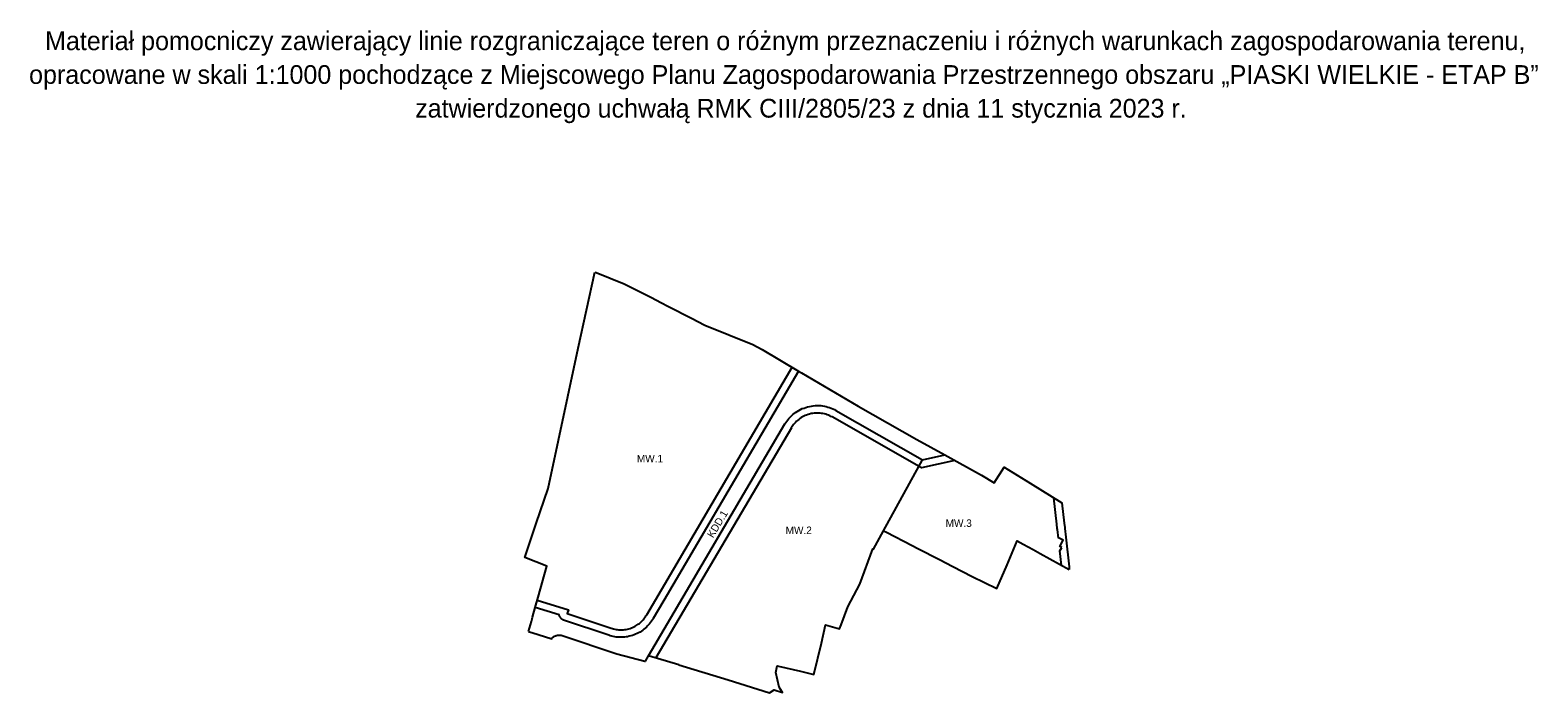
# Model space of a CAD drawing. Extents: x 7427825 to 7429032, y 5541325 to 5541855.
import ezdxf

# ---------------------------------------------------------------- set-up
doc = ezdxf.new("R2010")
doc.units = 0
for name, color, linetype in [('info', 7, 'Continuous'), ('LIN_Linia Zabudowy Nieprzekraczalna', 7, 'Continuous'), ('LIN_linie_rozgraniczajace', 7, 'Continuous'), ('TXT_oznaczenia_przeznaczen', 7, 'Continuous')]:
    doc.layers.add(name, color=color, linetype=linetype)

msp = doc.modelspace()

# ---------------------------------------------------------------- linework, layer by layer
at = {"layer": 'LIN_Linia Zabudowy Nieprzekraczalna'}
msp.add_line((7428649.8, 5541438.2), (7428651.3, 5541441), dxfattribs=at)
for points in [[(7428231.4, 5541398.8), (7428256.5, 5541391), (7428255.5, 5541388), (7428290.6, 5541376.3), (7428291.6, 5541376), (7428292.5, 5541375.7), (7428293.5, 5541375.5), (7428294.5, 5541375.3), (7428295.4, 5541375.2), (7428296.4, 5541375.1), (7428297.5, 5541375), (7428298.5, 5541375), (7428299.5, 5541375), (7428300.6, 5541375.1), (7428301.6, 5541375.2), (7428302.7, 5541375.4), (7428303.7, 5541375.6), (7428304.7, 5541375.9), (7428305.7, 5541376.2), (7428306.8, 5541376.6), (7428307.7, 5541377), (7428308.7, 5541377.4), (7428309.7, 5541377.9), (7428310.6, 5541378.4), (7428311.5, 5541379), (7428312.3, 5541379.6), (7428313.2, 5541380.2), (7428314, 5541380.8), (7428314.7, 5541381.5), (7428315.5, 5541382.3), (7428316.2, 5541383), (7428316.8, 5541383.7), (7428317.4, 5541384.5), (7428318, 5541385.3), (7428318.5, 5541386.1), (7428319.1, 5541387), (7428435.6, 5541585.3)], [(7428565.7, 5541510.6), (7428539, 5541504.6), (7428467.5, 5541545.4), (7428467.6, 5541545.4), (7428466.6, 5541545.9), (7428465.6, 5541546.4), (7428464.6, 5541546.8), (7428463.5, 5541547.2), (7428462.5, 5541547.6), (7428461.4, 5541547.9), (7428460.2, 5541548.1), (7428459.1, 5541548.3), (7428457.9, 5541548.5), (7428456.7, 5541548.6), (7428455.5, 5541548.6), (7428454.3, 5541548.6), (7428453, 5541548.5), (7428451.8, 5541548.3), (7428450.6, 5541548.1), (7428449.4, 5541547.8), (7428448.2, 5541547.4), (7428447.1, 5541547), (7428446, 5541546.6), (7428444.8, 5541546), (7428443.8, 5541545.5), (7428442.7, 5541544.9), (7428441.7, 5541544.2), (7428440.8, 5541543.5), (7428439.9, 5541542.7), (7428439, 5541542), (7428438.2, 5541541.1), (7428437.5, 5541540.3), (7428436.7, 5541539.4), (7428436.1, 5541538.6), (7428435.5, 5541537.7), (7428434.8, 5541536.7), (7428434.9, 5541536.8), (7428326.5, 5541352.5)], [(7428648.7, 5541448.5), (7428648, 5541455.2), (7428647.8, 5541456), (7428647.3, 5541459.6), (7428645, 5541480.7)], [(7428651.3, 5541441), (7428649.9, 5541441.8), (7428652.4, 5541446.7), (7428648.7, 5541448.6)], [(7428648.7, 5541448.6), (7428648.7, 5541448.5)], [(7428651.1, 5541426.8), (7428649.8, 5541438.2)]]:
    msp.add_lwpolyline(points, dxfattribs=at)
at = {"layer": 'LIN_linie_rozgraniczajace'}
for p, q in [((7428508.6, 5541454.3), (7428539.9, 5541511)), ((7428317.5, 5541350), (7428318, 5541349.9)), ((7428344.8, 5541347), (7428320.6, 5541354.3))]:
    msp.add_line(p, q, dxfattribs=at)
for points in [[(7428229.8, 5541393), (7428232.1, 5541401.2), (7428239.1, 5541426), (7428221.6, 5541433), (7428230.7, 5541460.2), (7428240.1, 5541488.2), (7428264.3, 5541600.4), (7428277.5, 5541661.4)], [(7428277.5, 5541661.4), (7428278.5, 5541661.1), (7428301, 5541651.9), (7428322.9, 5541641), (7428330.3, 5541637.2), (7428336.6, 5541634), (7428354.8, 5541624.6), (7428365.5, 5541619), (7428403.9, 5541603.4), (7428411.6, 5541599.5), (7428440.7, 5541582.2), (7428443.1, 5541580.8)], [(7428440.7, 5541582.2), (7428332.8, 5541398.5), (7428324.3, 5541384.1), (7428324.2, 5541383.9), (7428323.6, 5541382.9), (7428322.9, 5541381.9), (7428322.2, 5541380.9), (7428321.4, 5541379.9), (7428320.6, 5541379), (7428319.8, 5541378.1), (7428318.9, 5541377.2), (7428317.9, 5541376.3), (7428316.9, 5541375.5), (7428315.9, 5541374.7), (7428314.8, 5541373.9), (7428313.7, 5541373.2), (7428312.5, 5541372.6), (7428311.3, 5541372), (7428310.1, 5541371.4), (7428308.9, 5541370.9), (7428307.6, 5541370.5), (7428306.3, 5541370.1), (7428305.1, 5541369.8), (7428303.8, 5541369.5), (7428302.5, 5541369.3), (7428301.2, 5541369.1), (7428299.8, 5541369.1), (7428298.6, 5541369), (7428297.3, 5541369), (7428296, 5541369.1), (7428294.7, 5541369.2), (7428293.5, 5541369.4), (7428292.3, 5541369.6), (7428291.1, 5541369.9), (7428289.9, 5541370.2), (7428288.8, 5541370.6), (7428252.5, 5541382.7), (7428251.9, 5541383.1), (7428251.3, 5541383.6), (7428250.7, 5541384.1), (7428250.4, 5541384.4), (7428250.2, 5541384.7), (7428249.9, 5541385.1), (7428249.7, 5541385.4), (7428249.5, 5541385.8), (7428249.3, 5541386.1), (7428249.1, 5541386.5), (7428248.9, 5541387), (7428248.9, 5541387), (7428229.8, 5541393)], [(7428443.1, 5541580.8), (7428488.3, 5541554), (7428535.4, 5541527.4), (7428557.8, 5541515), (7428587, 5541498.9), (7428597.2, 5541492.6), (7428605.2, 5541505.2), (7428626, 5541492.4)], [(7428429.7, 5541539.8), (7428430.4, 5541540.9), (7428431.2, 5541542.1), (7428432, 5541543.2), (7428432.9, 5541544.2), (7428433.9, 5541545.3), (7428434.9, 5541546.3), (7428436, 5541547.3), (7428437.1, 5541548.2), (7428438.3, 5541549.1), (7428439.5, 5541549.9), (7428440.8, 5541550.7), (7428442.2, 5541551.4), (7428443.5, 5541552.1), (7428445, 5541552.6), (7428446.4, 5541553.1), (7428447.9, 5541553.6), (7428449.4, 5541553.9), (7428450.9, 5541554.2), (7428452.4, 5541554.4), (7428453.9, 5541554.5), (7428455.4, 5541554.6), (7428457, 5541554.6), (7428458.5, 5541554.5), (7428459.9, 5541554.3), (7428461.4, 5541554), (7428462.8, 5541553.7), (7428464.2, 5541553.3), (7428465.5, 5541552.9), (7428466.8, 5541552.4), (7428468.1, 5541551.9), (7428469.3, 5541551.3), (7428470.5, 5541550.6)], [(7428318, 5541349.9), (7428320.6, 5541354.3), (7428429.7, 5541539.8)], [(7428470.5, 5541550.6), (7428539.9, 5541511), (7428557.8, 5541515)], [(7428626, 5541492.4), (7428651.5, 5541476.8), (7428653.2, 5541460.3), (7428653.8, 5541457), (7428653.9, 5541456), (7428654.7, 5541449.2), (7428657.2, 5541425.4), (7428657.4, 5541423.3)], [(7428344.8, 5541347), (7428384.4, 5541335), (7428417.3, 5541324.5), (7428421.2, 5541326.9), (7428427.9, 5541324.7), (7428425.2, 5541329.1), (7428422.4, 5541340.9), (7428423.6, 5541346.2), (7428424.7, 5541346), (7428442.2, 5541341.8), (7428452.9, 5541339.3), (7428459.1, 5541364.3), (7428462.1, 5541379.1), (7428473.4, 5541375.7), (7428474.7, 5541379.1), (7428480.2, 5541393.3), (7428489.8, 5541411.6), (7428500, 5541439.9), (7428500.7, 5541439.5), (7428508.6, 5541454.3)], [(7428508.6, 5541454.3), (7428511, 5541453.2), (7428531.6, 5541442.4), (7428536.1, 5541440.1), (7428553.5, 5541431.2), (7428564.2, 5541425.8), (7428579.7, 5541417.8), (7428599.5, 5541408), (7428607.6, 5541427.1), (7428615.7, 5541446.2), (7428620.5, 5541443.5), (7428628.4, 5541439.2), (7428634, 5541436.2), (7428657.4, 5541423.3)], [(7428224.5, 5541373.7), (7428226.8, 5541381.8), (7428227.3, 5541383.7), (7428227.7, 5541385.2), (7428229.8, 5541393)], [(7428224.5, 5541373.7), (7428232.2, 5541371.3), (7428243, 5541367.9), (7428243.1, 5541368.2), (7428243.4, 5541368.6), (7428244, 5541369.1), (7428244.4, 5541369.3), (7428244.7, 5541369.6), (7428245, 5541369.8), (7428245.4, 5541370), (7428245.8, 5541370.1), (7428246.1, 5541370.3), (7428246.5, 5541370.4), (7428246.9, 5541370.5), (7428247.7, 5541370.7), (7428248.5, 5541370.8), (7428249.2, 5541370.8), (7428250, 5541370.8), (7428250.7, 5541370.6), (7428251.4, 5541370.4), (7428295.1, 5541355.8)], [(7428295.1, 5541355.8), (7428317.5, 5541350)]]:
    msp.add_lwpolyline(points, dxfattribs=at)

# ---------------------------------------------------------------- texts
at = {"layer": 'info'}
for s, p in [('Materiał pomocniczy zawierający linie rozgraniczające teren o różnym przeznaczeniu i różnych warunkach zagospodarowania terenu, ', (7427837.4, 5541839.1)), ('opracowane w skali 1:1000 pochodzące z Miejscowego Planu Zagospodarowania Przestrzennego obszaru „PIASKI WIELKIE - ETAP B” ', (7427824.6, 5541812.1)), ('zatwierdzonego uchwałą RMK CIII/2805/23 z dnia 11 stycznia 2023 r.', (7428133.7, 5541785.1))]:
    msp.add_text(s, height=15, dxfattribs=at).set_placement(p)
at = {"layer": 'TXT_oznaczenia_przeznaczen'}
for s, p in [('MW.1', (7428311.2, 5541509.1)), ('MW.2', (7428430.3, 5541451.7)), ('MW.3', (7428558.4, 5541457.4))]:
    msp.add_text(s, height=6, dxfattribs=at).set_placement(p)
msp.add_text('KDD.1', height=6, rotation=59.0189, dxfattribs=at).set_placement((7428372.2, 5541448.1))

doc.saveas('drawing.dxf')
